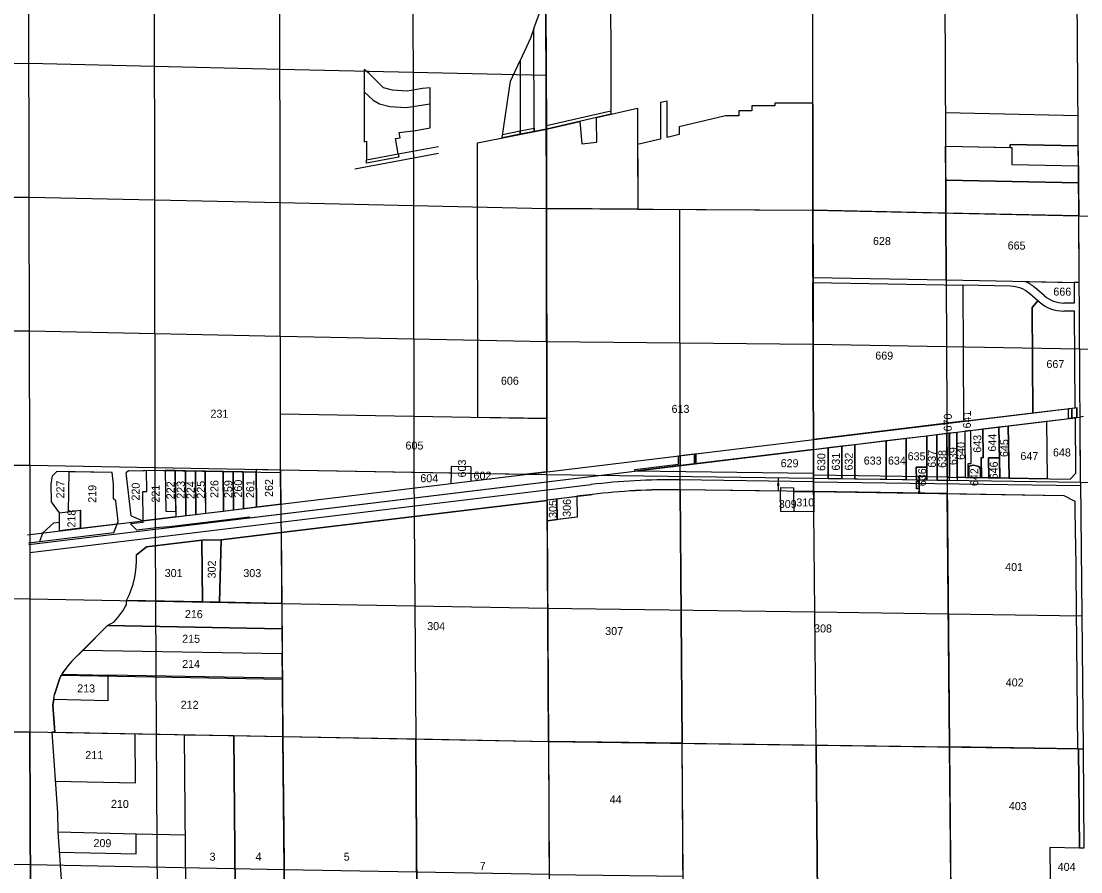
# Model space of a CAD drawing. Extents: x 582596 to 627039, y 145946 to 197316.
# Drawn here: x 594033 to 604584, y 171651 to 180120 of the extents above; entities that cross this region are included whole.
import ezdxf

# ---------------------------------------------------------------- set-up
doc = ezdxf.new("R2010")
doc.units = 0
for name, color, linetype in [('Defpoints 2', 7, 'Continuous'), ('E_RW_Existing', 7, 'Continuous'), ('E_RW_SixteenthLine', 7, 'Continuous'), ('P_RW_PropertyLine', 7, 'Continuous'), ('P_RW_QuarterLine', 7, 'Continuous'), ('P_RW_SectionLine', 7, 'Continuous'), ('ROW', 7, 'Continuous')]:
    doc.layers.add(name, color=color, linetype=linetype)

msp = doc.modelspace()

# ---------------------------------------------------------------- linework, layer by layer
at = {"layer": 'Defpoints'}
for p, q in [((594373, 172555), (595172, 172537)), ((594398, 172048), (595177, 172030)), ((595177, 172030), (595668, 172019)), ((594412, 171846), (595178, 171829))]:
    msp.add_line(p, q, dxfattribs=at)
for points in [[(601098, 175628), (601098, 175628)], [(601098, 175628), (601098, 175628)], [(601574, 175571), (601574, 175571)], [(601596, 175571), (601596, 175571)], [(602946, 175584), (602946, 175584)], [(602978, 175584), (602978, 175584)], [(601095, 175448), (601095, 175448)], [(601594, 175441), (601594, 175441)], [(602943, 175421), (602943, 175421)]]:
    msp.add_lwpolyline(points, dxfattribs=at)
at = {"layer": 'E_RW_Existing'}
for p, q in [((601913, 180868), (601916, 178237)), ((603228, 180849), (603239, 178209)), ((599905, 179193), (599262, 179046)), ((604568, 177518), (604518, 177519)), ((595103, 175643), (595077, 175622)), ((595129, 175195), (595077, 175622)), ((595253, 175640), (595103, 175643)), ((595253, 175651), (596615, 175625)), ((595253, 175651), (595253, 175640)), ((601923, 175617), (600143, 175641)), ((601923, 175617), (601923, 175603)), ((601923, 175603), (603252, 175583)), ((603252, 175583), (603252, 175580)), ((603252, 175580), (604476, 175561)), ((596307, 175175), (599268, 175534)), ((601921, 175437), (600581, 175455)), ((601594, 175476), (601724, 175474)), ((601594, 175476), (601594, 175441)), ((601724, 175474), (601724, 175439)), ((594975, 175343), (594952, 175366)), ((596622, 175028), (599269, 175349)), ((599269, 175354), (599719, 175408)), ((599269, 175354), (599269, 175349)), ((601724, 175439), (601924, 175437)), ((601924, 175437), (604416, 175399)), ((604416, 175399), (604524, 175341)), ((604524, 175341), (604527, 174969)), ((595247, 175130), (595245, 175146)), ((595511, 175090), (596306, 175186)), ((596306, 175186), (596307, 175175)), ((599270, 175147), (599369, 175159)), ((594107, 174925), (594955, 175028)), ((595247, 175130), (595123, 175115)), ((595123, 175115), (595183, 175055)), ((595183, 175055), (595412, 175083)), ((595412, 175083), (595511, 175090)), ((596622, 175028), (596026, 174956)), ((595833, 174953), (595282, 174886)), ((596026, 174956), (595833, 174953)), ((604532, 174969), (604527, 174969)), ((604532, 174969), (604551, 172876)), ((595282, 174886), (595179, 174802)), ((595082, 174310), (595082, 174352)), ((594552, 173761), (594894, 174102)), ((594894, 174102), (594958, 174140)), ((594422, 173589), (594364, 173417)), ((594349, 173311), (594364, 173417)), ((594368, 173040), (594349, 173311)), ((594339, 173040), (594395, 172239)), ((594368, 173040), (594339, 173040)), ((594395, 172239), (594398, 172048)), ((594398, 172048), (594434, 171527))]:
    msp.add_line(p, q, dxfattribs=at)
for points in [[(599905, 179227), (599905, 179193), (599262, 179046), (599262, 179080)], [(599142, 179056), (599142, 179022), (599002, 178994), (599002, 179028)], [(599002, 179028), (599002, 178994), (598822, 178958), (598827, 178993)], [(597788, 178798), (597794, 178765), (597472, 178706), (597472, 178740)], [(604606, 172875), (604615, 171887), (604570, 171887), (604561, 172876)]]:
    msp.add_lwpolyline(points, close=True, dxfattribs=at)
for points in [[(594220, 174939), (594249, 175025), (594357, 175124), (594416, 175131), (594416, 175226), (594334, 175333), (594331, 175515), (594345, 175593), (594389, 175636)], [(594951, 175366), (594954, 175510), (594940, 175626), (594389, 175636)], [(594955, 175028), (594999, 175140), (594975, 175343)], [(595129, 175195), (595245, 175146)]]:
    msp.add_lwpolyline(points, dxfattribs=at)
for centre, radius, start, end in [((600495, 169007), 6448, 89.2351, 96.9156), ((594292, 174759), 889, 332.8043, 2.7968), ((594292, 174759), 909, 317.1203, 330.4433), ((595094, 173217), 769, 134.924, 151.0654)]:
    msp.add_arc(centre, radius, start, end, dxfattribs=at)
at = {"layer": 'E_RW_SixteenthLine'}
for p, q in [((595363, 178341), (595358, 181003)), ((597933, 180940), (597938, 178283)), ((591466, 179688), (594110, 179701)), ((594110, 179701), (596611, 179643)), ((596611, 179643), (599260, 179581)), ((595367, 175673), (595363, 178341)), ((597938, 178283), (597942, 175626)), ((600595, 175585), (600590, 178245)), ((603239, 178209), (603252, 175547)), ((594115, 177032), (591476, 177033)), ((596614, 176982), (594115, 177032)), ((599266, 176928), (596614, 176982)), ((601919, 176902), (599266, 176928)), ((604572, 176854), (601919, 176902)), ((605896, 176823), (604572, 176854)), ((595381, 173021), (595367, 175673)), ((597942, 175626), (597961, 172974)), ((600614, 172931), (600595, 175585)), ((603252, 175547), (603277, 172894)), ((591480, 174379), (594119, 174370)), ((594119, 174370), (596628, 174324)), ((596628, 174324), (599275, 174276)), ((599275, 174276), (601935, 174240)), ((601935, 174240), (604594, 174201)), ((595396, 170370), (595381, 173021)), ((597961, 172974), (597980, 170320)), ((600633, 170288), (600614, 172931)), ((603277, 172894), (603300, 170254)), ((594124, 171722), (591481, 171734)), ((596652, 171670), (594124, 171722)), ((599289, 171624), (596652, 171670))]:
    msp.add_line(p, q, dxfattribs=at)
at = {"layer": 'P_RW_PropertyLine'}
for p, q in [((604460, 176164), (604460, 176264)), ((604495, 176268), (604544, 176274)), ((604495, 176168), (604495, 176268)), ((604527, 176272), (604544, 176274)), ((604544, 176174), (604544, 176274)), ((604243, 176138), (604527, 176172)), ((604544, 176174), (604495, 176168)), ((604527, 176172), (604544, 176174)), ((604527, 176172), (604531, 175618)), ((604544, 176174), (604577, 176178)), ((604610, 176183), (604577, 176179)), ((604582, 175527), (604577, 176178)), ((603277, 175571), (603274, 176020)), ((601922, 175856), (600737, 175713)), ((598314, 175685), (598313, 175620)), ((598511, 175682), (598314, 175685)), ((598511, 175682), (598510, 175616)), ((598313, 175620), (598311, 175518)), ((598510, 175616), (598509, 175542)), ((601923, 175567), (601926, 175234)), ((604531, 175618), (604476, 175561)), ((594119, 174829), (599707, 175506)), ((601922, 175535), (600583, 175553)), ((601922, 175535), (604581, 175496)), ((601724, 175439), (601726, 175236)), ((594416, 175044), (594416, 175225)), ((595282, 174886), (595833, 174953)), ((596628, 174324), (596009, 174336)), ((594127, 170399), (594121, 173044)), ((595172, 172537), (595168, 173025)), ((595178, 171829), (595177, 172030))]:
    msp.add_line(p, q, dxfattribs=at)
for points in [[(599256, 180908), (599900, 180898), (599905, 179193), (599262, 179046)], [(599002, 178994), (598822, 178958), (598905, 179524), (599000, 179728)], [(597788, 178798), (597759, 178951), (597807, 178959), (597797, 179011), (597958, 179031), (598107, 179058), (598105, 179457), (598030, 179448), (597877, 179423), (597731, 179432), (597642, 179455), (597495, 179601), (597447, 179638), (597448, 178919), (597472, 178924), (597472, 178740)], [(599262, 179046), (599595, 179122), (599616, 178900), (599765, 178914), (599763, 179129), (599760, 179160), (600170, 179254), (600173, 178248), (599265, 178254)], [(603237, 178877), (603881, 178863), (603881, 178893), (604558, 178878), (604556, 179178), (603235, 179206)], [(599262, 179046), (599265, 178254), (599267, 176163), (598581, 176175), (598577, 178910)], [(603898, 178694), (604559, 178680), (604560, 178511), (603238, 178538), (603237, 178877), (603897, 178863)], [(604558, 178878), (603881, 178893), (603881, 178863), (603897, 178863), (603898, 178694), (604559, 178680)], [(604560, 178511), (604563, 178181), (603239, 178209), (603238, 178538)], [(601916, 178237), (601923, 175567), (599268, 175602), (599265, 178254)], [(603243, 177544), (603239, 178209), (601916, 178237), (601918, 177569)], [(603239, 178209), (603243, 177544), (604568, 177518), (604563, 178181)], [(603408, 177490), (603417, 176137), (601922, 175956), (601917, 177519)], [(599039, 175606), (596616, 175650), (596615, 176211), (599267, 176163), (599268, 175634)], [(604460, 176264), (604495, 176268), (604495, 176168), (604460, 176164)], [(604544, 176174), (604495, 176168), (604495, 176268), (604544, 176274)], [(603870, 175571), (603777, 175572), (603769, 176080), (603861, 176092)], [(604250, 175565), (603870, 175571), (603861, 176092), (604243, 176138)], [(602846, 175553), (602845, 175968), (603051, 175993), (603051, 175680), (602945, 175681), (602946, 175551)], [(603051, 175993), (603150, 176005), (603152, 175548), (603052, 175550)], [(603252, 175547), (603152, 175548), (603150, 176005), (603250, 176017)], [(603277, 175579), (603252, 175580), (603250, 176017), (603275, 176020)], [(603352, 175545), (603277, 175546), (603274, 176020), (603348, 176029)], [(603432, 175577), (603351, 175578), (603348, 176029), (603429, 176039)], [(603489, 176046), (603429, 176039), (603432, 175577), (603462, 175577), (603461, 175715), (603491, 175715)], [(603461, 175715), (603491, 175715), (603489, 176046), (603609, 176061), (603611, 175774), (603593, 175775), (603594, 175575), (603586, 175575), (603585, 175660), (603567, 175687), (603515, 175701), (603470, 175690), (603470, 175577), (603462, 175577)], [(603609, 176061), (603769, 176080), (603774, 175772), (603664, 175774), (603667, 175574), (603594, 175575), (603593, 175775), (603611, 175774)], [(601922, 175856), (602067, 175874), (602068, 175565), (601923, 175567)], [(602067, 175874), (602204, 175891), (602205, 175563), (602068, 175565)], [(602204, 175891), (602334, 175906), (602335, 175561), (602205, 175563)], [(602334, 175906), (602645, 175944), (602646, 175556), (602335, 175561)], [(602645, 175944), (602845, 175968), (602846, 175553), (602646, 175556)], [(600593, 175695), (600144, 175641), (600142, 175655), (600578, 175708), (600578, 175793), (600593, 175795)], [(600593, 175795), (600737, 175812), (600737, 175713), (600593, 175695)], [(600752, 175714), (600737, 175713), (600737, 175812), (600752, 175814)], [(603777, 175572), (603667, 175574), (603664, 175774), (603774, 175772)], [(603052, 175550), (602946, 175551), (602945, 175681), (603051, 175680)], [(603470, 175577), (603470, 175690), (603515, 175701), (603567, 175687), (603585, 175660), (603586, 175575)], [(594509, 175634), (594500, 175236), (594622, 175251), (594621, 175071), (594990, 175115), (594999, 175140), (594975, 175343), (594952, 175366), (594954, 175510), (594940, 175626)], [(595468, 175647), (595472, 175241), (595572, 175239), (595572, 175186), (595247, 175146), (595244, 175438), (595284, 175437), (595282, 175650)], [(595568, 175645), (595468, 175647), (595472, 175241), (595572, 175239)], [(595668, 175643), (595568, 175645), (595572, 175186), (595672, 175198)], [(595768, 175641), (595668, 175643), (595672, 175198), (595772, 175210)], [(595868, 175639), (595768, 175641), (595772, 175210), (595872, 175222)], [(596043, 175636), (595863, 175639), (595867, 175222), (596047, 175243)], [(596143, 175634), (596043, 175636), (596047, 175243), (596147, 175256)], [(596243, 175632), (596143, 175634), (596147, 175256), (596246, 175268)], [(596374, 175630), (596243, 175632), (596246, 175268), (596377, 175284)], [(596616, 175650), (596374, 175655), (596377, 175284), (596619, 175313)], [(601573, 175566), (601575, 175566), (601574, 175571), (601574, 175571)], [(600596, 175455), (600614, 172931), (603277, 172894), (603254, 175417), (601924, 175437), (601926, 175234), (601596, 175238), (601594, 175441)], [(601566, 175497), (601566, 175516), (601572, 175516), (601572, 175497)], [(596622, 175028), (596628, 174324), (596640, 172998), (599282, 172950), (599269, 175349)], [(599269, 175353), (599368, 175366), (599369, 175159), (599270, 175147)], [(599368, 175366), (599567, 175390), (599568, 175183), (599369, 175159)], [(601571, 175446), (601573, 175446), (601572, 175441), (601572, 175441)], [(604527, 174969), (604532, 174969), (604551, 172876), (603277, 172894), (603254, 175417), (604416, 175399), (604524, 175341)], [(594416, 175046), (594416, 175226), (594625, 175251), (594625, 175071)], [(596622, 175028), (596628, 174324), (596009, 174336), (596026, 174956)], [(595833, 174953), (596026, 174956), (596009, 174336), (595839, 174339)], [(594894, 174102), (596630, 174070), (596633, 173820), (594648, 173856)], [(594368, 173040), (596640, 172998), (596635, 173579), (594896, 173610), (594896, 173355), (594357, 173365), (594349, 173311)], [(596640, 172998), (597961, 172974), (597980, 170320), (597831, 170322), (597835, 170572), (597635, 170576), (597631, 170326), (596664, 170342)], [(597961, 172974), (599282, 172950), (599296, 170298), (597980, 170320)], [(599282, 172950), (599289, 171624), (600624, 171609), (600614, 172931)], [(601947, 172913), (601971, 170278), (600733, 170287), (600732, 170507), (600632, 170508), (600614, 172931)], [(601947, 172913), (603277, 172894), (603300, 170254), (603214, 170255), (603211, 170608), (602980, 170612), (602984, 170259), (601971, 170278)], [(604561, 172875), (604570, 171887), (604274, 171892), (604277, 171571), (604618, 171567), (604618, 171553), (603288, 171574), (603277, 172894)]]:
    msp.add_lwpolyline(points, close=True, dxfattribs=at)
for points in [[(599262, 179046), (599142, 179022), (599139, 180046), (599217, 180263), (599258, 180262), (599262, 179046)], [(599142, 179022), (599139, 180046), (599104, 179949), (599000, 179728), (599002, 178994), (599142, 179022)], [(597448, 179415), (597537, 179332), (597601, 179296), (597704, 179269), (597865, 179259), (598106, 179297)], [(601915, 179304), (601538, 179303), (601538, 179278), (601307, 179278), (601307, 179228), (601177, 179228), (601177, 179178), (601047, 179178), (600586, 179067), (600586, 178991), (600466, 178962), (600466, 179325), (600400, 179309), (600400, 178946), (600171, 178891), (600173, 178248), (601916, 178237), (601915, 179304)], [(603882, 177481), (603408, 177490), (603417, 176137), (604107, 176221)], [(604031, 177528), (604518, 177519), (604519, 177314), (604414, 177314)], [(604221, 177385), (604127, 177467)], [(604107, 176221), (604099, 177269), (604157, 177335), (604075, 177406)], [(604169, 177325), (604157, 177335), (604099, 177269), (604107, 176221), (604527, 176272), (604520, 177234), (604414, 177234)], [(601572, 175446), (601574, 175566)], [(599270, 175147), (599282, 172950), (600614, 172931), (600596, 175455), (600581, 175455)], [(599719, 175408), (599567, 175390), (599568, 175183), (599270, 175147)], [(595179, 174802), (595282, 174886), (595833, 174953), (595839, 174339)], [(596628, 174324), (596630, 174070), (594894, 174102), (594958, 174140)], [(595839, 174339), (595082, 174352)], [(595082, 174310), (595082, 174352), (596628, 174324)], [(594434, 173610), (596635, 173570), (596633, 173820)], [(596633, 173820), (594648, 173856), (594552, 173761)], [(594896, 173610), (594896, 173355), (594357, 173365), (594364, 173417), (594422, 173589)], [(594439, 173618), (594896, 173610)], [(596150, 173007), (596174, 170353), (595683, 170364), (595659, 173016), (596150, 173007)], [(596640, 172998), (596664, 170342), (596174, 170353), (596150, 173007), (596640, 172998)]]:
    msp.add_lwpolyline(points, dxfattribs=at)
for centre, radius, start, end in [((603876, 177178), 303, 48.9033, 88.881), ((603876, 177178), 383, 48.9033, 66.0526), ((604412, 177604), 290, 228.9047, 270.5065), ((604412, 177604), 370, 228.9035, 270.4109), ((600495, 169007), 6547, 89.2351, 96.9156), ((600501, 168894), 6561, 89.3012, 96.8494), ((594292, 174759), 889, 332.8043, 2.7968), ((594292, 174759), 909, 317.1203, 330.4433), ((595094, 173217), 768, 134.9239, 149.2024), ((594503, 173561), 85.9, 138.1961, 161.3627)]:
    msp.add_arc(centre, radius, start, end, dxfattribs=at)
at = {"layer": 'P_RW_QuarterLine'}
for points in [[(602974, 175564), (602981, 175564), (602978, 175584), (602978, 175584)], [(602948, 175464), (602949, 175540), (602973, 175540), (602972, 175464)], [(602972, 175441), (602979, 175441), (602975, 175421), (602975, 175421)]]:
    msp.add_lwpolyline(points, close=True, dxfattribs=at)
msp.add_lwpolyline([(602976, 175441), (602977, 175564)], dxfattribs=at)
at = {"layer": 'P_RW_SectionLine'}
for p, q in [((594113, 178369), (594107, 181033)), ((596612, 178313), (596609, 180972)), ((599265, 178254), (599256, 180908)), ((604563, 178181), (604543, 180829)), ((591473, 178363), (594113, 178369)), ((594113, 178369), (596612, 178313)), ((594118, 175696), (594113, 178369)), ((596612, 178313), (599265, 178254)), ((596616, 175650), (596612, 178313)), ((599265, 178254), (601916, 178237)), ((599268, 175602), (599265, 178254)), ((601916, 178237), (604563, 178181)), ((601923, 175567), (601916, 178237)), ((604563, 178181), (605888, 178149)), ((604582, 175527), (604563, 178181)), ((594118, 175696), (591479, 175702)), ((596616, 175650), (594118, 175696)), ((594118, 175696), (594121, 173044)), ((599268, 175602), (596616, 175650)), ((596616, 175650), (596640, 172998)), ((601923, 175567), (599268, 175602)), ((599268, 175602), (599282, 172950)), ((604582, 175527), (601923, 175567)), ((601947, 172913), (601923, 175567)), ((605905, 175497), (604582, 175527)), ((604582, 175527), (604606, 172875)), ((591480, 173056), (594121, 173044)), ((594121, 173044), (596640, 172998)), ((594121, 173044), (594127, 170399)), ((596640, 172998), (599282, 172950)), ((596640, 172998), (596664, 170342)), ((599282, 172950), (601947, 172913)), ((599282, 172950), (599296, 170298)), ((601947, 172913), (604606, 172875)), ((601947, 172913), (601971, 170278))]:
    msp.add_line(p, q, dxfattribs=at)
at = {"layer": 'ROW'}
for p, q in [((597788, 178798), (598188, 178871)), ((597355, 178651), (598189, 178805)), ((594097, 175007), (604527, 176272)), ((594109, 174909), (604527, 176172))]:
    msp.add_line(p, q, dxfattribs=at)

# ---------------------------------------------------------------- texts
at = {"layer": 'Defpoints 2'}
for s, rotation, p in [('628', 359.5042, (602514, 177892)), ('665', 359.5042, (603855, 177847)), ('666', 359.5042, (604310, 177388)), ('669', 359.5042, (602537, 176751)), ('667', 359.5042, (604241, 176667)), ('670', 89.5042, (603298, 176035)), ('641', 89.5042, (603489, 176065)), ('643', 89.5042, (603592, 175823)), ('644', 89.5042, (603740, 175834)), ('639', 89.5042, (603350, 175700)), ('640', 89.5042, (603429, 175752)), ('645', 89.5042, (603860, 175780)), ('630', 89.5042, (602039, 175641)), ('631', 89.5042, (602184, 175645)), ('632', 89.5042, (602312, 175646)), ('633', 359.5042, (602422, 175706)), ('634', 359.5042, (602663, 175706)), ('635', 359.5042, (602859, 175749)), ('637', 89.5042, (603140, 175674)), ('638', 89.5042, (603243, 175672)), ('647', 359.5042, (603982, 175751)), ('648', 359.5042, (604306, 175787)), ('603', 89.5042, (598461, 175577)), ('629', 359.5042, (601595, 175680)), ('636', 89.5042, (603043, 175490)), ('642', 89.5042, (603562, 175491)), ('646', 89.5042, (603756, 175558)), ('262', 89.5042, (596539, 175383)), ('604', 359.5042, (598007, 175530)), ('602', 359.5042, (598537, 175556)), ('227', 89.5042, (594462, 175368)), ('219', 89.5042, (594780, 175325)), ('220', 89.5042, (595212, 175347)), ('221', 89.5042, (595411, 175327)), ('222', 89.5042, (595560, 175360)), ('223', 89.5042, (595661, 175365)), ('224', 89.5042, (595760, 175362)), ('225', 89.5042, (595861, 175366)), ('226', 89.5042, (595996, 175373)), ('259', 89.5042, (596134, 175372)), ('260', 89.5042, (596232, 175377)), ('261', 89.5042, (596352, 175372)), ('305', 89.5042, (599366, 175174)), ('306', 89.5042, (599505, 175185)), ('309', 359.5042, (601576, 175274)), ('218', 89.5042, (594573, 175078)), ('302', 89.5042, (595970, 174572)), ('401', 359.5042, (603830, 174647)), ('301', 359.5042, (595462, 174586)), ('303', 359.5042, (596245, 174586)), ('216', 359.5042, (595663, 174178)), ('304', 359.5042, (598076, 174058)), ('307', 359.5042, (599848, 174009)), ('308', 359.5042, (601928, 174035)), ('215', 359.5042, (595636, 173932)), ('214', 359.5042, (595636, 173681)), ('402', 359.5042, (603836, 173498)), ('213', 359.5042, (594591, 173438)), ('212', 359.5042, (595621, 173275)), ('211', 359.5042, (594671, 172774)), ('44', 359.5042, (599892, 172333)), ('210', 359.5042, (594927, 172288)), ('403', 359.5042, (603867, 172267)), ('209', 359.5042, (594753, 171898)), ('404', 359.5042, (604353, 171661))]:
    msp.add_text(s, height=79.7, rotation=rotation, dxfattribs=at).set_placement(p)
for s, p in [('606', (598810, 176500)), ('613', (600509, 176220)), ('231', (595918, 176172)), ('605', (597860, 175855)), ('310', (601751, 175289)), ('3', (595909, 171762)), ('4', (596367, 171762)), ('5', (597245, 171762)), ('7', (598599, 171670))]:
    msp.add_text(s, height=79.7, dxfattribs=at).set_placement(p)
at = {"layer": 'P_RW_PropertyLine'}
msp.add_text('130.03', height=4, rotation=89.2351, dxfattribs=at).set_placement((601571, 175498))
at = {"layer": 'P_RW_QuarterLine'}
msp.add_text('163.00', height=16, rotation=89.1526, dxfattribs=at).set_placement((602968, 175468))

doc.saveas('drawing.dxf')
